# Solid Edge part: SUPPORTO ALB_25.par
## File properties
Subject: SUPPORTO ALBERO_25
Author: f_grande
Template: Normal.par
Last saved by: f_grande
Revision: 3
Application: Solid Edge
Material: Alluminio, 1060
Stile della faccia: Alluminio
Stile di riempimento: ANSI38(Alluminio)
Stile virtuale: Alluminio lucidato
Coef. of Thermal Exp: 0.0
Thermal Conductivity: 221.0
Specific Heat: 920.0
Modulus of Elasticity: 68947570000.0
Poisson's Ratio: 0.33
Yield Stress: 27579028.0
Ultimate Stress: 68947570.0
Elongation: 0.0
Tipo di contenuto documento: 0
Densità: 2712,000 kg/m^3
Precisione: 0,990
Document Number: KR0104
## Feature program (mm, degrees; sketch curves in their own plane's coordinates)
sketch for "unnamed Protrusion 1" #1 plane through (0, 0, 0) normal (0, -1, 0) x-axis (1, 0, 0)
  line (-20.3573, 22.7546) -> (4.6427, 35.1211)
  line (4.6427, 35.1211) -> (4.6427, 39.7546)
  line (24.6427, 39.7546) -> (4.6427, 39.7546)
  line (24.6427, 39.7546) -> (24.6427, 35.1211)
  line (49.6427, 22.7546) -> (24.6427, 35.1211)
  line (49.6427, 22.7546) -> (49.6427, 12.7546)
  line (23.5103, -0.1721) -> (49.6427, 12.7546)
  line (-20.3573, 12.7546) -> (5.6987, -0.1341)
  line (-20.3573, 22.7546) -> (-20.3573, 12.7546)
sketch for "unnamed Protrusion 1" #2 plane through (0, 0, 0) normal (0, -1, 0) x-axis (1, 0, 0)
  circle centre (14.6427, 17.7546) radius 12.5
extrude "unnamed Protrusion 1" add finite 10 along +normal
sketch for "ExtrudedProtrusion_2" #1 plane through (14.6427, -10, 17.7546) normal (0, -1, 0) x-axis (0.896336, 0, -0.443375)
  line (-18.7176, 15.2856) -> (-0.7909, 24.1531)
  line (-0.7909, 24.1531) -> (1.2839, 19.9587)
  line (-18.7176, 15.2856) -> (-16.6428, 11.0912)
sketch for "ExtrudedProtrusion_2" #2 plane through (14.6427, -10, 17.7546) normal (0, -1, 0) x-axis (0.896336, 0, -0.443375)
  circle centre (0, 0) radius 12.5
extrude "ExtrudedProtrusion_2" add finite 15 along +normal
fillet "Rotondo_1" radius 2
fillet "Rotondo_2" radius 1
fillet "Rotondo_3" radius 0.5
fillet "Rotondo_4" radius 0.5
sketch for "ExtrudedCutout_1" plane through (14.6427, -25, 19.0046) normal (0, -1, 0) x-axis (1, 0, 0)
  line (-1, 7.7374) -> (-1, 25.4607)
  line (-1, 25.4607) -> (1, 25.4607)
  line (1, 25.4607) -> (1, 7.7374)
  line (-1, 7.7374) -> (1, 7.7374)
extrude "ExtrudedCutout_1" cut finite 57.6581 along -normal
sketch for "ExtrudedCutout_3" plane through (-20.3573, 0, 0) normal (1, 0, 0) x-axis (0, 1, 0)
  circle centre (-17.5, 36.7546) radius 1.75
extrude "ExtrudedCutout_3" cut finite 76.522 along +normal
sketch for "ExtrudedCutout_4" #1 plane through (-7.3293, -10, 17.3709) normal (0, -1, 0) x-axis (0.896336, 0, -0.443375)
  circle centre (44.6216, 22.5002) radius 3
sketch for "ExtrudedCutout_4" #2 plane through (-7.3293, -10, 17.3709) normal (0, -1, 0) x-axis (0.896336, 0, -0.443375)
  circle centre (-5.5733, -2.3288) radius 3
extrude "ExtrudedCutout_4" cut finite 155.7522 along -normal
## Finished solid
Body 1: solid body, 35 faces, 95 edges, 58 vertices.
  Faces by surface: plane 16, cylinder 15, torus 4
  Edges by curve: line 52, circle 39, intersection 4
Bounding box of the edges (mm; curved faces can reach further): 70.000 x 25.000 x 42.000, from (-20.3573, -25, -2.2454) to (49.6427, 0, 39.7546).
Cylindrical faces by radius (mm): R0.5 x2, R1 x4, R1.75 x2, R2 x3, R3 x2, R12.5 x1, R20 x1
Toroidal faces (ring radius, tube radius in mm): R2.5 r0.5 x2, R13 r0.5 x1, R19.5 r0.5 x1
Planar faces by outward normal: +x 3, +y 1, +z 2, -x 3, -y 3, oblique 4
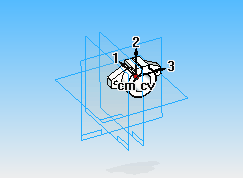
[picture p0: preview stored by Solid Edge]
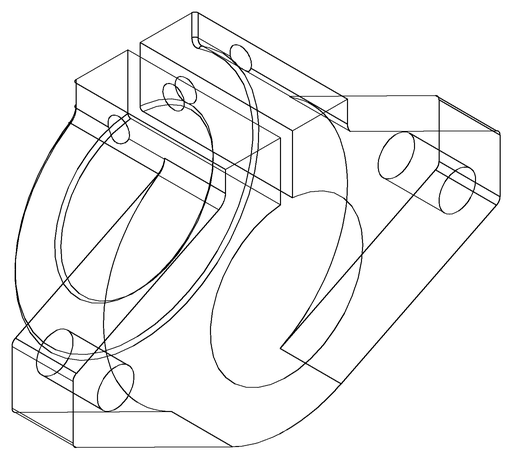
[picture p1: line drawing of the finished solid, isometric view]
